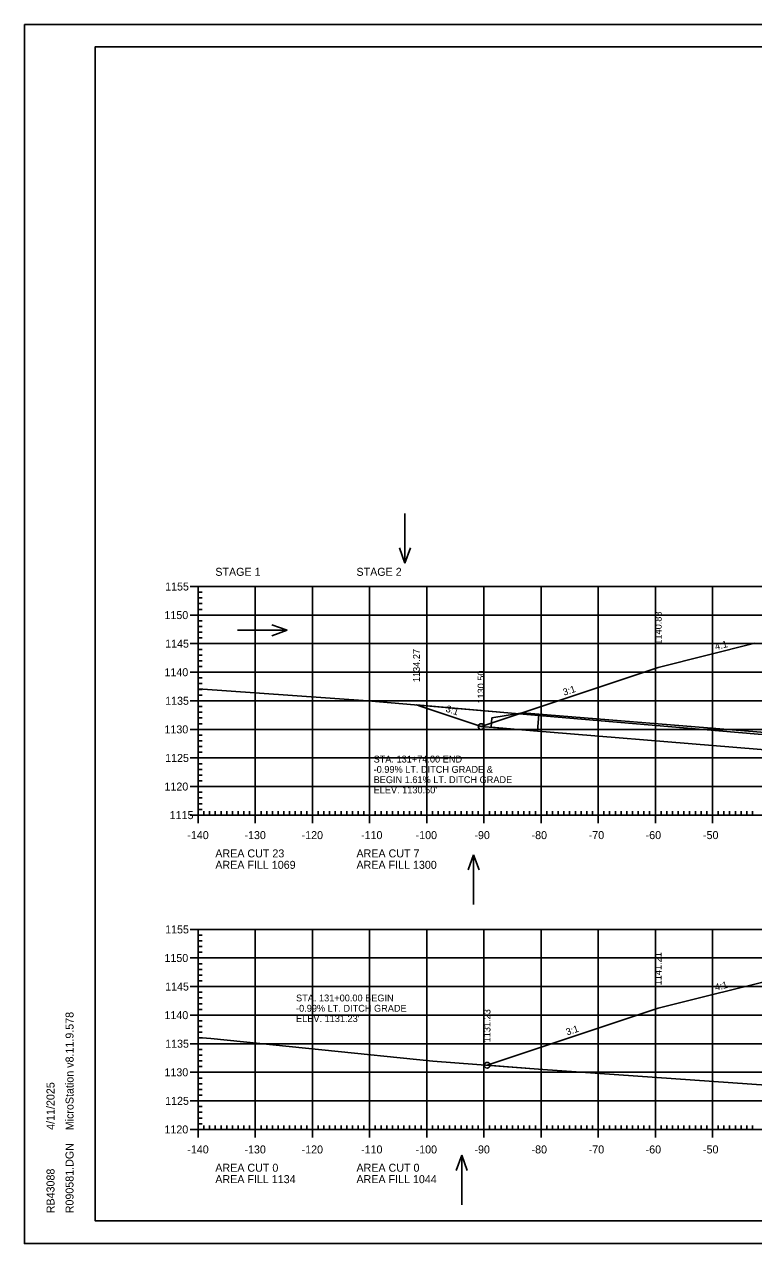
# Model space of a CAD drawing. Extents: x 1322838 to 1324533, y 339903 to 351025.
# Drawn here: x 1323533.3 to 1323660.9, y 341823.2 to 342036.5 of the extents above; entities that cross this region are included whole.
import ezdxf

# ---------------------------------------------------------------- set-up
doc = ezdxf.new("R2010")
doc.units = 0
for name, color, linetype in [('1', 7, 'Continuous'), ('R_Axis', 7, 'Continuous'), ('R_Axis Annot', 7, 'Continuous'), ('R_Border', 7, 'Continuous'), ('R_Drive', 7, 'Continuous'), ('R_Exist Surface', 7, 'Continuous'), ('R_Fin Surface', 7, 'Continuous'), ('R_Fin Surface Annot', 7, 'Continuous'), ('R_Grid', 7, 'Continuous'), ('R_No Plot', 7, 'Continuous'), ('R_Water', 7, 'Continuous'), ('R_Water Annot', 7, 'Continuous')]:
    doc.layers.add(name, color=color, linetype=linetype)

msp = doc.modelspace()

# ---------------------------------------------------------------- linework, layer by layer
at = {"layer": '1'}
msp.add_lwpolyline([(1323623.35, 341915.82), (1323623.11, 341912.83), (1323614.99, 341913.5), (1323615.13, 341915.16), (1323620.47, 341916.06)], close=True, dxfattribs=at)
at = {"layer": 'R_Axis'}
for p, q in [((1323562.32, 341938.14), (1323565.12, 341938.14)), ((1323563.72, 341898.14), (1323563.72, 341938.14)), ((1323563.72, 341937.14), (1323564.42, 341937.14)), ((1323563.72, 341936.14), (1323564.42, 341936.14)), ((1323563.72, 341935.14), (1323564.42, 341935.14)), ((1323563.72, 341934.14), (1323564.42, 341934.14)), ((1323562.32, 341933.14), (1323565.12, 341933.14)), ((1323563.72, 341932.14), (1323564.42, 341932.14)), ((1323563.72, 341931.14), (1323564.42, 341931.14)), ((1323563.72, 341930.14), (1323564.42, 341930.14)), ((1323563.72, 341929.14), (1323564.42, 341929.14)), ((1323562.32, 341928.14), (1323565.12, 341928.14)), ((1323563.72, 341927.14), (1323564.42, 341927.14)), ((1323563.72, 341926.14), (1323564.42, 341926.14)), ((1323563.72, 341925.14), (1323564.42, 341925.14)), ((1323562.32, 341923.14), (1323565.12, 341923.14)), ((1323563.72, 341924.14), (1323564.42, 341924.14)), ((1323563.72, 341922.14), (1323564.42, 341922.14)), ((1323563.72, 341921.14), (1323564.42, 341921.14)), ((1323563.72, 341920.14), (1323564.42, 341920.14)), ((1323563.72, 341919.14), (1323564.42, 341919.14)), ((1323562.32, 341918.14), (1323565.12, 341918.14)), ((1323563.72, 341917.14), (1323564.42, 341917.14)), ((1323563.72, 341916.14), (1323564.42, 341916.14)), ((1323563.72, 341915.14), (1323564.42, 341915.14)), ((1323563.72, 341914.14), (1323564.42, 341914.14)), ((1323562.32, 341913.14), (1323565.12, 341913.14)), ((1323563.72, 341912.14), (1323564.42, 341912.14)), ((1323563.72, 341911.14), (1323564.42, 341911.14)), ((1323563.72, 341910.14), (1323564.42, 341910.14)), ((1323562.32, 341908.14), (1323565.12, 341908.14)), ((1323563.72, 341909.14), (1323564.42, 341909.14)), ((1323563.72, 341907.14), (1323564.42, 341907.14)), ((1323563.72, 341906.14), (1323564.42, 341906.14)), ((1323563.72, 341905.14), (1323564.42, 341905.14)), ((1323563.72, 341904.14), (1323564.42, 341904.14)), ((1323562.32, 341903.14), (1323565.12, 341903.14)), ((1323563.72, 341902.14), (1323564.42, 341902.14)), ((1323563.72, 341901.14), (1323564.42, 341901.14)), ((1323563.72, 341900.14), (1323564.42, 341900.14)), ((1323563.72, 341896.74), (1323563.72, 341899.54)), ((1323563.72, 341899.14), (1323564.42, 341899.14)), ((1323573.72, 341896.74), (1323573.72, 341899.54)), ((1323583.72, 341896.74), (1323583.72, 341899.54)), ((1323593.72, 341896.74), (1323593.72, 341899.54)), ((1323603.72, 341896.74), (1323603.72, 341899.54)), ((1323613.72, 341896.74), (1323613.72, 341899.54)), ((1323623.72, 341896.74), (1323623.72, 341899.54)), ((1323633.72, 341896.74), (1323633.72, 341899.54)), ((1323643.72, 341896.74), (1323643.72, 341899.54)), ((1323653.72, 341896.74), (1323653.72, 341899.54)), ((1323562.32, 341898.14), (1323565.12, 341898.14)), ((1323563.72, 341898.14), (1323843.72, 341898.14)), ((1323564.72, 341898.14), (1323564.72, 341898.84)), ((1323565.72, 341898.14), (1323565.72, 341898.84)), ((1323566.72, 341898.14), (1323566.72, 341898.84)), ((1323567.72, 341898.14), (1323567.72, 341898.84)), ((1323568.72, 341898.14), (1323568.72, 341898.84)), ((1323569.72, 341898.14), (1323569.72, 341898.84)), ((1323570.72, 341898.14), (1323570.72, 341898.84)), ((1323571.72, 341898.14), (1323571.72, 341898.84)), ((1323572.72, 341898.14), (1323572.72, 341898.84)), ((1323574.72, 341898.14), (1323574.72, 341898.84)), ((1323575.72, 341898.14), (1323575.72, 341898.84)), ((1323576.72, 341898.14), (1323576.72, 341898.84)), ((1323577.72, 341898.14), (1323577.72, 341898.84)), ((1323578.72, 341898.14), (1323578.72, 341898.84)), ((1323579.72, 341898.14), (1323579.72, 341898.84)), ((1323580.72, 341898.14), (1323580.72, 341898.84)), ((1323581.72, 341898.14), (1323581.72, 341898.84)), ((1323582.72, 341898.14), (1323582.72, 341898.84)), ((1323584.72, 341898.14), (1323584.72, 341898.84)), ((1323585.72, 341898.14), (1323585.72, 341898.84)), ((1323586.72, 341898.14), (1323586.72, 341898.84)), ((1323587.72, 341898.14), (1323587.72, 341898.84)), ((1323588.72, 341898.14), (1323588.72, 341898.84)), ((1323589.72, 341898.14), (1323589.72, 341898.84)), ((1323590.72, 341898.14), (1323590.72, 341898.84)), ((1323591.72, 341898.14), (1323591.72, 341898.84)), ((1323592.72, 341898.14), (1323592.72, 341898.84)), ((1323594.72, 341898.14), (1323594.72, 341898.84)), ((1323595.72, 341898.14), (1323595.72, 341898.84)), ((1323596.72, 341898.14), (1323596.72, 341898.84)), ((1323597.72, 341898.14), (1323597.72, 341898.84)), ((1323598.72, 341898.14), (1323598.72, 341898.84)), ((1323599.72, 341898.14), (1323599.72, 341898.84)), ((1323600.72, 341898.14), (1323600.72, 341898.84)), ((1323601.72, 341898.14), (1323601.72, 341898.84)), ((1323602.72, 341898.14), (1323602.72, 341898.84)), ((1323604.72, 341898.14), (1323604.72, 341898.84)), ((1323605.72, 341898.14), (1323605.72, 341898.84)), ((1323606.72, 341898.14), (1323606.72, 341898.84)), ((1323607.72, 341898.14), (1323607.72, 341898.84)), ((1323608.72, 341898.14), (1323608.72, 341898.84)), ((1323609.72, 341898.14), (1323609.72, 341898.84)), ((1323610.72, 341898.14), (1323610.72, 341898.84)), ((1323611.72, 341898.14), (1323611.72, 341898.84)), ((1323612.72, 341898.14), (1323612.72, 341898.84)), ((1323614.72, 341898.14), (1323614.72, 341898.84)), ((1323615.72, 341898.14), (1323615.72, 341898.84)), ((1323616.72, 341898.14), (1323616.72, 341898.84)), ((1323617.72, 341898.14), (1323617.72, 341898.84)), ((1323618.72, 341898.14), (1323618.72, 341898.84)), ((1323619.72, 341898.14), (1323619.72, 341898.84)), ((1323620.72, 341898.14), (1323620.72, 341898.84)), ((1323621.72, 341898.14), (1323621.72, 341898.84)), ((1323622.72, 341898.14), (1323622.72, 341898.84)), ((1323624.72, 341898.14), (1323624.72, 341898.84)), ((1323625.72, 341898.14), (1323625.72, 341898.84)), ((1323626.72, 341898.14), (1323626.72, 341898.84)), ((1323627.72, 341898.14), (1323627.72, 341898.84)), ((1323628.72, 341898.14), (1323628.72, 341898.84)), ((1323629.72, 341898.14), (1323629.72, 341898.84)), ((1323630.72, 341898.14), (1323630.72, 341898.84)), ((1323631.72, 341898.14), (1323631.72, 341898.84)), ((1323632.72, 341898.14), (1323632.72, 341898.84)), ((1323634.72, 341898.14), (1323634.72, 341898.84)), ((1323635.72, 341898.14), (1323635.72, 341898.84)), ((1323636.72, 341898.14), (1323636.72, 341898.84)), ((1323637.72, 341898.14), (1323637.72, 341898.84)), ((1323638.72, 341898.14), (1323638.72, 341898.84)), ((1323639.72, 341898.14), (1323639.72, 341898.84)), ((1323640.72, 341898.14), (1323640.72, 341898.84)), ((1323641.72, 341898.14), (1323641.72, 341898.84)), ((1323642.72, 341898.14), (1323642.72, 341898.84)), ((1323644.72, 341898.14), (1323644.72, 341898.84)), ((1323645.72, 341898.14), (1323645.72, 341898.84)), ((1323646.72, 341898.14), (1323646.72, 341898.84)), ((1323647.72, 341898.14), (1323647.72, 341898.84)), ((1323648.72, 341898.14), (1323648.72, 341898.84)), ((1323649.72, 341898.14), (1323649.72, 341898.84)), ((1323650.72, 341898.14), (1323650.72, 341898.84)), ((1323651.72, 341898.14), (1323651.72, 341898.84)), ((1323652.72, 341898.14), (1323652.72, 341898.84)), ((1323654.72, 341898.14), (1323654.72, 341898.84)), ((1323655.72, 341898.14), (1323655.72, 341898.84)), ((1323656.72, 341898.14), (1323656.72, 341898.84)), ((1323657.72, 341898.14), (1323657.72, 341898.84)), ((1323658.72, 341898.14), (1323658.72, 341898.84)), ((1323659.72, 341898.14), (1323659.72, 341898.84)), ((1323660.72, 341898.14), (1323660.72, 341898.84)), ((1323562.32, 341878.14), (1323565.12, 341878.14)), ((1323563.72, 341843.14), (1323563.72, 341878.14)), ((1323563.72, 341877.14), (1323564.42, 341877.14)), ((1323563.72, 341876.14), (1323564.42, 341876.14)), ((1323563.72, 341875.14), (1323564.42, 341875.14)), ((1323563.72, 341874.14), (1323564.42, 341874.14)), ((1323562.32, 341873.14), (1323565.12, 341873.14)), ((1323563.72, 341872.14), (1323564.42, 341872.14)), ((1323563.72, 341871.14), (1323564.42, 341871.14)), ((1323563.72, 341870.14), (1323564.42, 341870.14)), ((1323562.32, 341868.14), (1323565.12, 341868.14)), ((1323563.72, 341869.14), (1323564.42, 341869.14)), ((1323563.72, 341867.14), (1323564.42, 341867.14)), ((1323563.72, 341866.14), (1323564.42, 341866.14)), ((1323563.72, 341865.14), (1323564.42, 341865.14)), ((1323562.32, 341863.14), (1323565.12, 341863.14)), ((1323563.72, 341864.14), (1323564.42, 341864.14)), ((1323563.72, 341862.14), (1323564.42, 341862.14)), ((1323563.72, 341861.14), (1323564.42, 341861.14)), ((1323563.72, 341860.14), (1323564.42, 341860.14)), ((1323563.72, 341859.14), (1323564.42, 341859.14)), ((1323562.32, 341858.14), (1323565.12, 341858.14)), ((1323563.72, 341857.14), (1323564.42, 341857.14)), ((1323563.72, 341856.14), (1323564.42, 341856.14)), ((1323563.72, 341855.14), (1323564.42, 341855.14)), ((1323562.32, 341853.14), (1323565.12, 341853.14)), ((1323563.72, 341854.14), (1323564.42, 341854.14)), ((1323563.72, 341852.14), (1323564.42, 341852.14)), ((1323563.72, 341851.14), (1323564.42, 341851.14)), ((1323563.72, 341850.14), (1323564.42, 341850.14)), ((1323562.32, 341848.14), (1323565.12, 341848.14)), ((1323563.72, 341849.14), (1323564.42, 341849.14)), ((1323563.72, 341847.14), (1323564.42, 341847.14)), ((1323563.72, 341846.14), (1323564.42, 341846.14)), ((1323563.72, 341845.14), (1323564.42, 341845.14)), ((1323563.72, 341841.74), (1323563.72, 341844.54)), ((1323563.72, 341844.14), (1323564.42, 341844.14)), ((1323564.72, 341843.14), (1323564.72, 341843.84)), ((1323565.72, 341843.14), (1323565.72, 341843.84)), ((1323566.72, 341843.14), (1323566.72, 341843.84)), ((1323567.72, 341843.14), (1323567.72, 341843.84)), ((1323568.72, 341843.14), (1323568.72, 341843.84)), ((1323569.72, 341843.14), (1323569.72, 341843.84)), ((1323570.72, 341843.14), (1323570.72, 341843.84)), ((1323571.72, 341843.14), (1323571.72, 341843.84)), ((1323572.72, 341843.14), (1323572.72, 341843.84)), ((1323573.72, 341841.74), (1323573.72, 341844.54)), ((1323574.72, 341843.14), (1323574.72, 341843.84)), ((1323575.72, 341843.14), (1323575.72, 341843.84)), ((1323576.72, 341843.14), (1323576.72, 341843.84)), ((1323577.72, 341843.14), (1323577.72, 341843.84)), ((1323578.72, 341843.14), (1323578.72, 341843.84)), ((1323579.72, 341843.14), (1323579.72, 341843.84)), ((1323580.72, 341843.14), (1323580.72, 341843.84)), ((1323581.72, 341843.14), (1323581.72, 341843.84)), ((1323582.72, 341843.14), (1323582.72, 341843.84)), ((1323583.72, 341841.74), (1323583.72, 341844.54)), ((1323584.72, 341843.14), (1323584.72, 341843.84)), ((1323585.72, 341843.14), (1323585.72, 341843.84)), ((1323586.72, 341843.14), (1323586.72, 341843.84)), ((1323587.72, 341843.14), (1323587.72, 341843.84)), ((1323588.72, 341843.14), (1323588.72, 341843.84)), ((1323589.72, 341843.14), (1323589.72, 341843.84)), ((1323590.72, 341843.14), (1323590.72, 341843.84)), ((1323591.72, 341843.14), (1323591.72, 341843.84)), ((1323592.72, 341843.14), (1323592.72, 341843.84)), ((1323593.72, 341841.74), (1323593.72, 341844.54)), ((1323594.72, 341843.14), (1323594.72, 341843.84)), ((1323595.72, 341843.14), (1323595.72, 341843.84)), ((1323596.72, 341843.14), (1323596.72, 341843.84)), ((1323597.72, 341843.14), (1323597.72, 341843.84)), ((1323598.72, 341843.14), (1323598.72, 341843.84)), ((1323599.72, 341843.14), (1323599.72, 341843.84)), ((1323600.72, 341843.14), (1323600.72, 341843.84)), ((1323601.72, 341843.14), (1323601.72, 341843.84)), ((1323602.72, 341843.14), (1323602.72, 341843.84)), ((1323603.72, 341841.74), (1323603.72, 341844.54)), ((1323604.72, 341843.14), (1323604.72, 341843.84)), ((1323605.72, 341843.14), (1323605.72, 341843.84)), ((1323606.72, 341843.14), (1323606.72, 341843.84)), ((1323607.72, 341843.14), (1323607.72, 341843.84)), ((1323608.72, 341843.14), (1323608.72, 341843.84)), ((1323609.72, 341843.14), (1323609.72, 341843.84)), ((1323610.72, 341843.14), (1323610.72, 341843.84)), ((1323611.72, 341843.14), (1323611.72, 341843.84)), ((1323612.72, 341843.14), (1323612.72, 341843.84)), ((1323613.72, 341841.74), (1323613.72, 341844.54)), ((1323614.72, 341843.14), (1323614.72, 341843.84)), ((1323615.72, 341843.14), (1323615.72, 341843.84)), ((1323616.72, 341843.14), (1323616.72, 341843.84)), ((1323617.72, 341843.14), (1323617.72, 341843.84)), ((1323618.72, 341843.14), (1323618.72, 341843.84)), ((1323619.72, 341843.14), (1323619.72, 341843.84)), ((1323620.72, 341843.14), (1323620.72, 341843.84)), ((1323621.72, 341843.14), (1323621.72, 341843.84)), ((1323622.72, 341843.14), (1323622.72, 341843.84)), ((1323623.72, 341841.74), (1323623.72, 341844.54)), ((1323624.72, 341843.14), (1323624.72, 341843.84)), ((1323625.72, 341843.14), (1323625.72, 341843.84)), ((1323626.72, 341843.14), (1323626.72, 341843.84)), ((1323627.72, 341843.14), (1323627.72, 341843.84)), ((1323628.72, 341843.14), (1323628.72, 341843.84)), ((1323629.72, 341843.14), (1323629.72, 341843.84)), ((1323630.72, 341843.14), (1323630.72, 341843.84)), ((1323631.72, 341843.14), (1323631.72, 341843.84)), ((1323632.72, 341843.14), (1323632.72, 341843.84)), ((1323633.72, 341841.74), (1323633.72, 341844.54)), ((1323634.72, 341843.14), (1323634.72, 341843.84)), ((1323635.72, 341843.14), (1323635.72, 341843.84)), ((1323636.72, 341843.14), (1323636.72, 341843.84)), ((1323637.72, 341843.14), (1323637.72, 341843.84)), ((1323638.72, 341843.14), (1323638.72, 341843.84)), ((1323639.72, 341843.14), (1323639.72, 341843.84)), ((1323640.72, 341843.14), (1323640.72, 341843.84)), ((1323641.72, 341843.14), (1323641.72, 341843.84)), ((1323642.72, 341843.14), (1323642.72, 341843.84)), ((1323643.72, 341841.74), (1323643.72, 341844.54)), ((1323644.72, 341843.14), (1323644.72, 341843.84)), ((1323645.72, 341843.14), (1323645.72, 341843.84)), ((1323646.72, 341843.14), (1323646.72, 341843.84)), ((1323647.72, 341843.14), (1323647.72, 341843.84)), ((1323648.72, 341843.14), (1323648.72, 341843.84)), ((1323649.72, 341843.14), (1323649.72, 341843.84)), ((1323650.72, 341843.14), (1323650.72, 341843.84)), ((1323651.72, 341843.14), (1323651.72, 341843.84)), ((1323652.72, 341843.14), (1323652.72, 341843.84)), ((1323653.72, 341841.74), (1323653.72, 341844.54)), ((1323654.72, 341843.14), (1323654.72, 341843.84)), ((1323655.72, 341843.14), (1323655.72, 341843.84)), ((1323656.72, 341843.14), (1323656.72, 341843.84)), ((1323657.72, 341843.14), (1323657.72, 341843.84)), ((1323658.72, 341843.14), (1323658.72, 341843.84)), ((1323659.72, 341843.14), (1323659.72, 341843.84)), ((1323660.72, 341843.14), (1323660.72, 341843.84)), ((1323562.32, 341843.14), (1323565.12, 341843.14)), ((1323563.72, 341843.14), (1323843.72, 341843.14))]:
    msp.add_line(p, q, dxfattribs=at)
at = {"layer": 'R_Border'}
for p, q in [((1323545.72, 342032.6), (1323861.9, 342032.6)), ((1323545.72, 341827.14), (1323545.72, 342032.6)), ((1323545.72, 341827.14), (1323545.72, 341827.14)), ((1323861.9, 341827.14), (1323545.72, 341827.14))]:
    msp.add_line(p, q, dxfattribs=at)
at = {"layer": 'R_Exist Surface'}
for points in [[(1323563.72, 341920.25), (1323574.48, 341919.49), (1323593.38, 341918.15), (1323630.81, 341914.91), (1323664.46, 341912.05)], [(1323563.72, 341859.25), (1323565.91, 341859.05), (1323604.8, 341855.09), (1323624.05, 341853.64), (1323663.1, 341850.86)]]:
    msp.add_lwpolyline(points, dxfattribs=at)
at = {"layer": 'R_Fin Surface'}
for points in [[(1323601.92, 341917.41), (1323602.77, 341917.13), (1323613.23, 341913.64), (1323644.21, 341923.97), (1323644.22, 341923.97), (1323661.12, 341928.2)], [(1323614.26, 341854.38), (1323614.27, 341854.37), (1323644.21, 341864.36), (1323653.31, 341866.63), (1323661.12, 341868.58), (1323666.22, 341869.86), (1323671.11, 341870.05), (1323672.22, 341870.1), (1323674.22, 341870.14), (1323685.76, 341870.37), (1323703.72, 341870.73), (1323733.22, 341870.14), (1323735.22, 341870.1), (1323741.22, 341869.86), (1323744.37, 341869.07), (1323746.31, 341868.58), (1323755.05, 341866.4), (1323763.22, 341864.36), (1323805.2, 341850.36)]]:
    msp.add_lwpolyline(points, dxfattribs=at)
at = {"layer": 'R_Grid'}
for p, q in [((1323563.72, 341938.14), (1323843.72, 341938.14)), ((1323563.72, 341898.14), (1323563.72, 341938.14)), ((1323573.72, 341898.14), (1323573.72, 341938.14)), ((1323583.72, 341898.14), (1323583.72, 341938.14)), ((1323593.72, 341898.14), (1323593.72, 341938.14)), ((1323603.72, 341898.14), (1323603.72, 341938.14)), ((1323613.72, 341898.14), (1323613.72, 341938.14)), ((1323623.72, 341898.14), (1323623.72, 341938.14)), ((1323633.72, 341898.14), (1323633.72, 341938.14)), ((1323643.72, 341898.14), (1323643.72, 341938.14)), ((1323653.72, 341898.14), (1323653.72, 341938.14)), ((1323563.72, 341933.14), (1323843.72, 341933.14)), ((1323563.72, 341928.14), (1323843.72, 341928.14)), ((1323563.72, 341923.14), (1323843.72, 341923.14)), ((1323563.72, 341918.14), (1323843.72, 341918.14)), ((1323563.72, 341913.14), (1323843.72, 341913.14)), ((1323563.72, 341908.14), (1323843.72, 341908.14)), ((1323563.72, 341903.14), (1323843.72, 341903.14)), ((1323563.72, 341898.14), (1323843.72, 341898.14)), ((1323563.72, 341878.14), (1323843.72, 341878.14)), ((1323563.72, 341843.14), (1323563.72, 341878.14)), ((1323573.72, 341843.14), (1323573.72, 341878.14)), ((1323583.72, 341843.14), (1323583.72, 341878.14)), ((1323593.72, 341843.14), (1323593.72, 341878.14)), ((1323603.72, 341843.14), (1323603.72, 341878.14)), ((1323613.72, 341843.14), (1323613.72, 341878.14)), ((1323623.72, 341843.14), (1323623.72, 341878.14)), ((1323633.72, 341843.14), (1323633.72, 341878.14)), ((1323643.72, 341843.14), (1323643.72, 341878.14)), ((1323653.72, 341843.14), (1323653.72, 341878.14)), ((1323563.72, 341873.14), (1323843.72, 341873.14)), ((1323563.72, 341868.14), (1323843.72, 341868.14)), ((1323563.72, 341863.14), (1323843.72, 341863.14)), ((1323563.72, 341858.14), (1323843.72, 341858.14)), ((1323563.72, 341853.14), (1323843.72, 341853.14)), ((1323563.72, 341848.14), (1323843.72, 341848.14)), ((1323563.72, 341843.14), (1323843.72, 341843.14))]:
    msp.add_line(p, q, dxfattribs=at)
at = {"layer": 'R_No Plot'}
for p, q in [((1323533.31, 342036.5), (1323866.65, 342036.5)), ((1323533.31, 341823.17), (1323866.65, 341823.17))]:
    msp.add_line(p, q, dxfattribs=at)
for points in [[(1323533.31, 342036.5), (1323866.65, 342036.5), (1323866.65, 341823.16), (1323533.31, 341823.16)], [(1323779.64, 342032.6), (1323799.26, 342032.6), (1323799.26, 342022.72), (1323815.37, 342022.72), (1323838.57, 342022.72), (1323838.57, 341990.05), (1323861.77, 341990.05), (1323861.9, 341827.14), (1323545.72, 341827.14), (1323545.72, 342032.6)], [(1323601.92, 341917.41), (1323619.87, 341915.86), (1323613.23, 341913.64), (1323602.77, 341917.13), (1323601.92, 341917.41)]]:
    msp.add_lwpolyline(points, close=True, dxfattribs=at)
for points in [[(1323661.12, 341928.2), (1323644.22, 341923.97), (1323644.21, 341923.97), (1323619.87, 341915.86), (1323630.81, 341914.91), (1323664.46, 341912.05)], [(1323661.12, 341868.58), (1323653.31, 341866.63), (1323644.21, 341864.36), (1323614.28, 341854.38), (1323624.05, 341853.64), (1323663.1, 341850.86)]]:
    msp.add_lwpolyline(points, dxfattribs=at)
for centre in [(1323613.23, 341913.64), (1323613.23, 341913.64), (1323614.27, 341854.37), (1323614.27, 341854.37)]:
    msp.add_circle(centre, 0.5, dxfattribs=at)
at = {"layer": 'R_Water'}
for p, q in [((1323620.47, 341916.06), (1323685.16, 341910.75)), ((1323613.23, 341913.64), (1323685.04, 341907.76))]:
    msp.add_line(p, q, dxfattribs=at)
at = {"layer": 'R_Water Annot'}
for p, q in [((1323599.9, 341950.94), (1323599.9, 341942.25)), ((1323599.9, 341942.25), (1323598.93, 341944.91)), ((1323599.9, 341942.25), (1323600.87, 341944.91)), ((1323579.27, 341930.49), (1323576.61, 341931.46)), ((1323570.58, 341930.49), (1323579.27, 341930.49)), ((1323579.27, 341930.49), (1323576.61, 341929.53)), ((1323611.91, 341891.21), (1323610.94, 341888.55)), ((1323611.91, 341882.52), (1323611.91, 341891.21)), ((1323611.91, 341891.21), (1323612.88, 341888.55)), ((1323609.86, 341838.61), (1323608.89, 341835.95)), ((1323609.86, 341829.92), (1323609.86, 341838.61)), ((1323609.86, 341838.61), (1323610.82, 341835.95))]:
    msp.add_line(p, q, dxfattribs=at)

# ---------------------------------------------------------------- texts
at = {"layer": 'R_Axis Annot'}
for s, p in [('STAGE 1', (1323566.72, 341940.01)), ('STAGE 2', (1323591.42, 341940.01)), ('1155', (1323557.94, 341937.44)), ('1150', (1323557.82, 341932.44)), ('1145', (1323557.94, 341927.44)), ('1140', (1323557.82, 341922.44)), ('1135', (1323557.94, 341917.44)), ('1130', (1323557.82, 341912.44)), ('1125', (1323557.94, 341907.44)), ('1120', (1323557.82, 341902.44)), ('1115', (1323558.73, 341897.44)), ('-140', (1323561.82, 341893.94)), ('-130', (1323571.82, 341893.94)), ('-120', (1323581.82, 341893.94)), ('-110', (1323592.22, 341893.94)), ('-100', (1323601.77, 341893.94)), ('-90', (1323612.06, 341893.94)), ('-80', (1323622.06, 341893.94)), ('-70', (1323632.06, 341893.94)), ('-60', (1323642.02, 341893.94)), ('-50', (1323652.06, 341893.94)), ('AREA CUT 23', (1323566.72, 341890.74)), ('AREA CUT 7', (1323591.42, 341890.74)), ('AREA FILL 1069', (1323566.72, 341888.74)), ('AREA FILL 1300', (1323591.42, 341888.74)), ('1155', (1323557.94, 341877.44)), ('1150', (1323557.82, 341872.44)), ('1145', (1323557.94, 341867.44)), ('1140', (1323557.82, 341862.44)), ('1135', (1323557.94, 341857.44)), ('1130', (1323557.82, 341852.44)), ('1125', (1323557.94, 341847.44)), ('1120', (1323557.82, 341842.44)), ('-140', (1323561.82, 341838.94)), ('-130', (1323571.82, 341838.94)), ('-120', (1323581.82, 341838.94)), ('-110', (1323592.22, 341838.94)), ('-100', (1323601.77, 341838.94)), ('-90', (1323612.06, 341838.94)), ('-80', (1323622.06, 341838.94)), ('-70', (1323632.06, 341838.94)), ('-60', (1323642.02, 341838.94)), ('-50', (1323652.06, 341838.94)), ('AREA CUT 0', (1323566.72, 341835.74)), ('AREA FILL 1134', (1323566.72, 341833.74)), ('AREA CUT 0', (1323591.42, 341835.74)), ('AREA FILL 1044', (1323591.42, 341833.74))]:
    msp.add_text(s, height=1.4, dxfattribs=at).set_placement(p)
at = {"layer": 'R_Border'}
for s, p in [('MicroStation v8.11.9.578', (1323541.91, 341843)), ('4/11/2025', (1323538.58, 341843.07)), ('R090581.DGN', (1323541.91, 341828.47)), ('RB43088', (1323538.58, 341828.47))]:
    msp.add_text(s, height=1.4, rotation=90, dxfattribs=at).set_placement(p)
at = {"layer": 'R_Drive'}
for s, p in [('STA. 131+74.00 END ', (1323594.42, 341907.34)), ('-0.99% LT. DITCH GRADE &', (1323594.42, 341905.54)), ('BEGIN 1.61% LT. DITCH GRADE', (1323594.42, 341903.74)), ("ELEV. 1130.50'", (1323594.42, 341901.94)), ('STA. 131+00.00 BEGIN', (1323580.85, 341865.54)), ('-0.99% LT. DITCH GRADE', (1323580.85, 341863.74)), ("ELEV. 1131.23'", (1323580.85, 341861.94))]:
    msp.add_text(s, height=1.2, dxfattribs=at).set_placement(p)
at = {"layer": 'R_Fin Surface Annot'}
for s, rotation, p in [('1140.83', 90, (1323644.82, 341927.97)), ('1134.27', 90, (1323602.52, 341921.41)), ('4:1', 14.0362, (1323654.29, 341927.01)), ('1130.50', 90, (1323613.83, 341917.64)), ('3:1', 18.4355, (1323627.77, 341919.02)), ('3:1', 341.5666, (1323606.94, 341916.27)), ('1141.21', 90, (1323644.81, 341868.36)), ('4:1', 14.0362, (1323654.29, 341867.39)), ('1131.23', 90, (1323614.86, 341858.38)), ('1131.23', 90, (1323614.87, 341858.37)), ('3:1', 18.4349, (1323628.3, 341859.58))]:
    msp.add_text(s, height=1.2, rotation=rotation, dxfattribs=at).set_placement(p)

doc.saveas('drawing.dxf')
